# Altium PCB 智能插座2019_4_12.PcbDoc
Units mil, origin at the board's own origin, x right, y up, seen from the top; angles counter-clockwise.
Board outline 3149.61 x 3089.41 mil, 2 copper layers (Top Layer, Bottom Layer); 84 components, 62 nets, 274 pads, 96 vias.
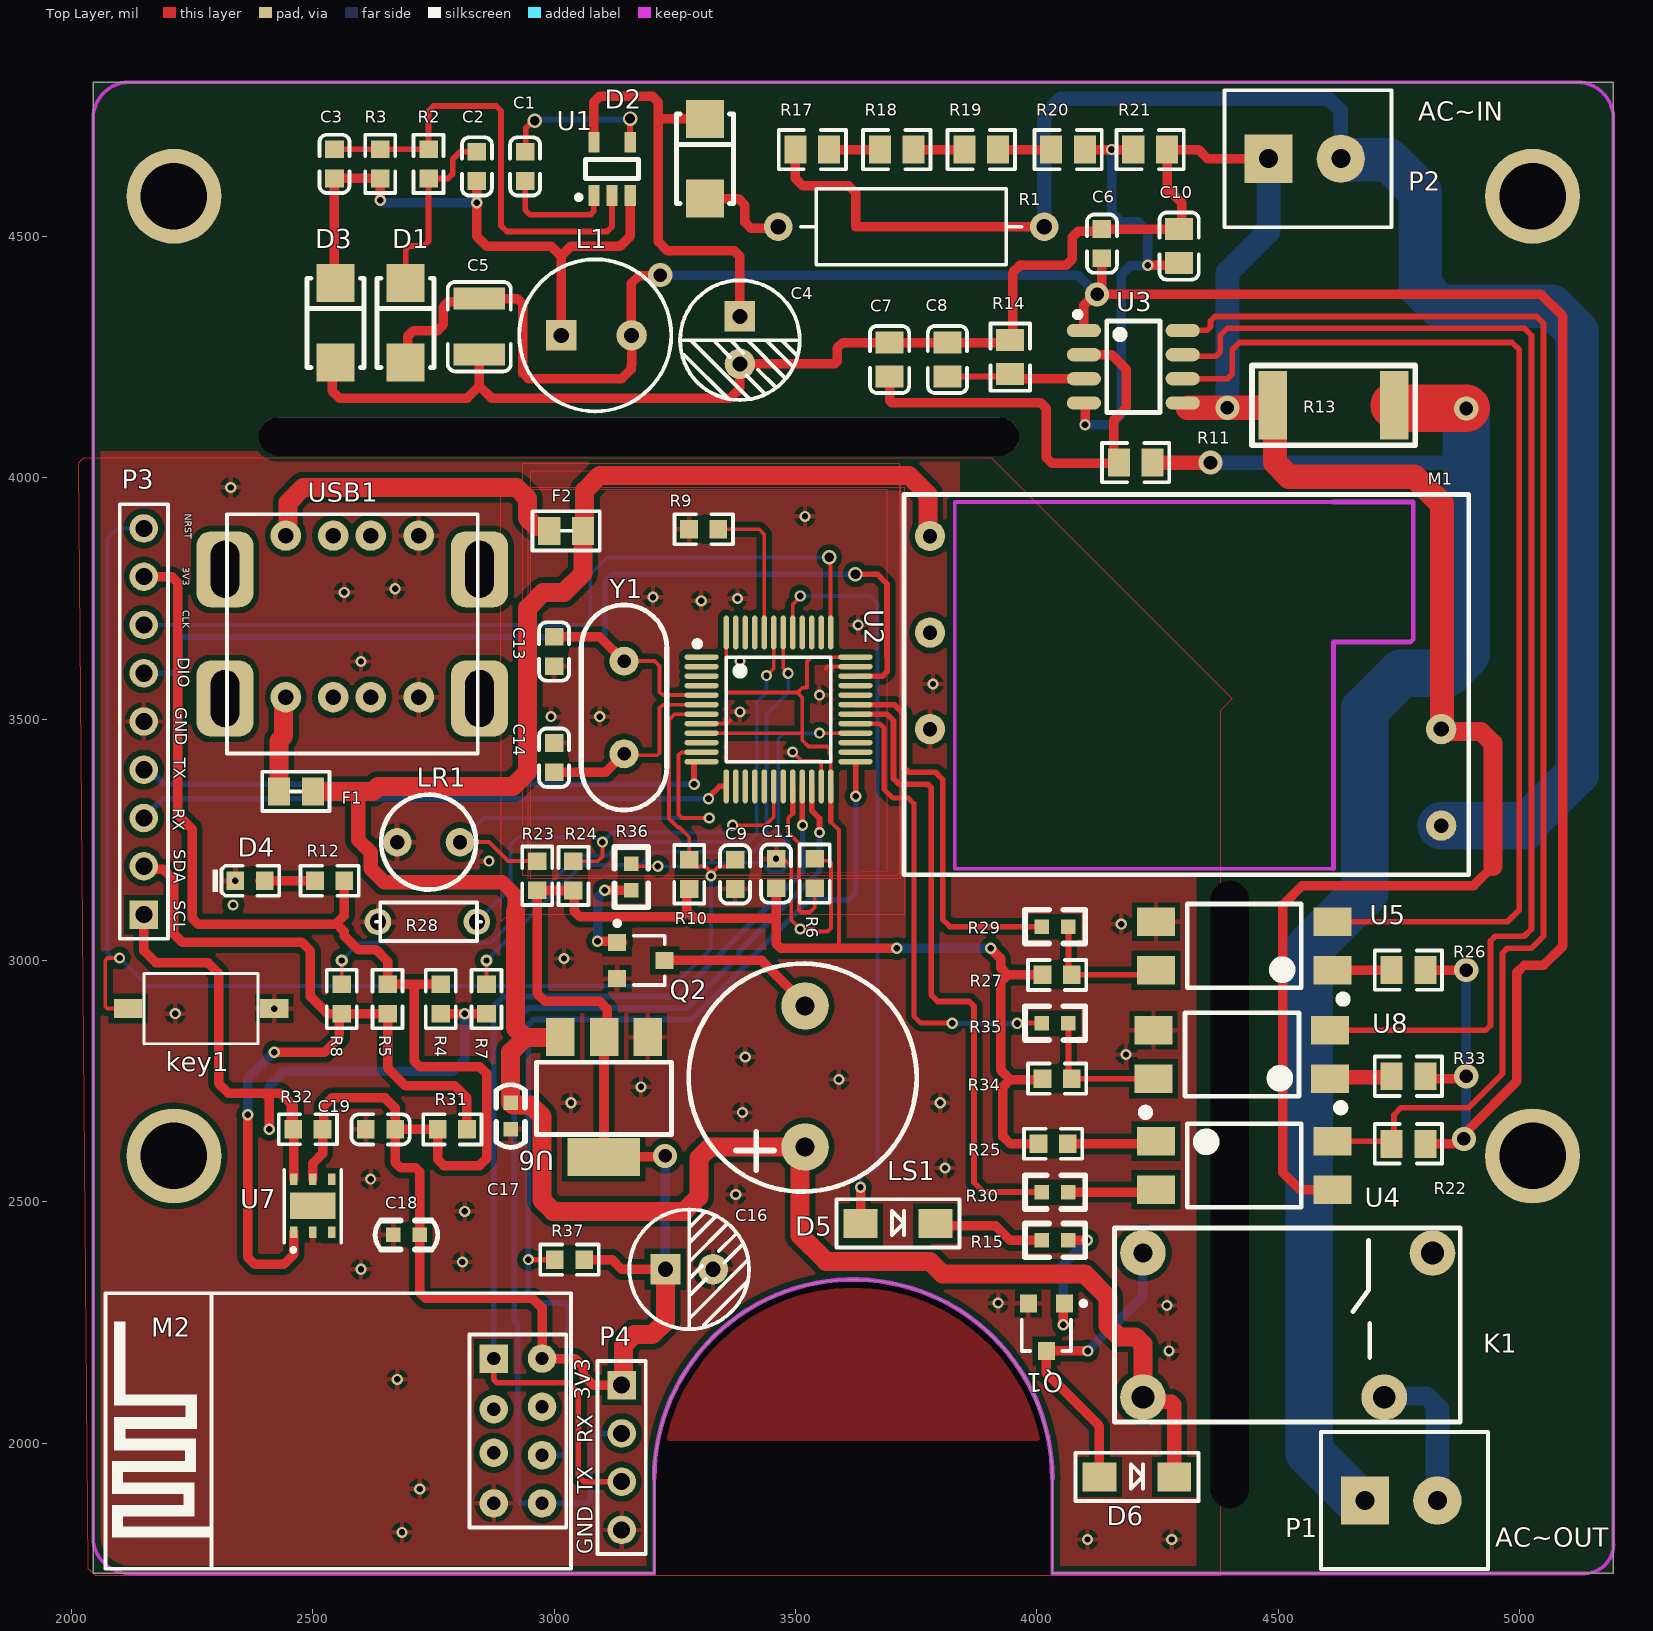
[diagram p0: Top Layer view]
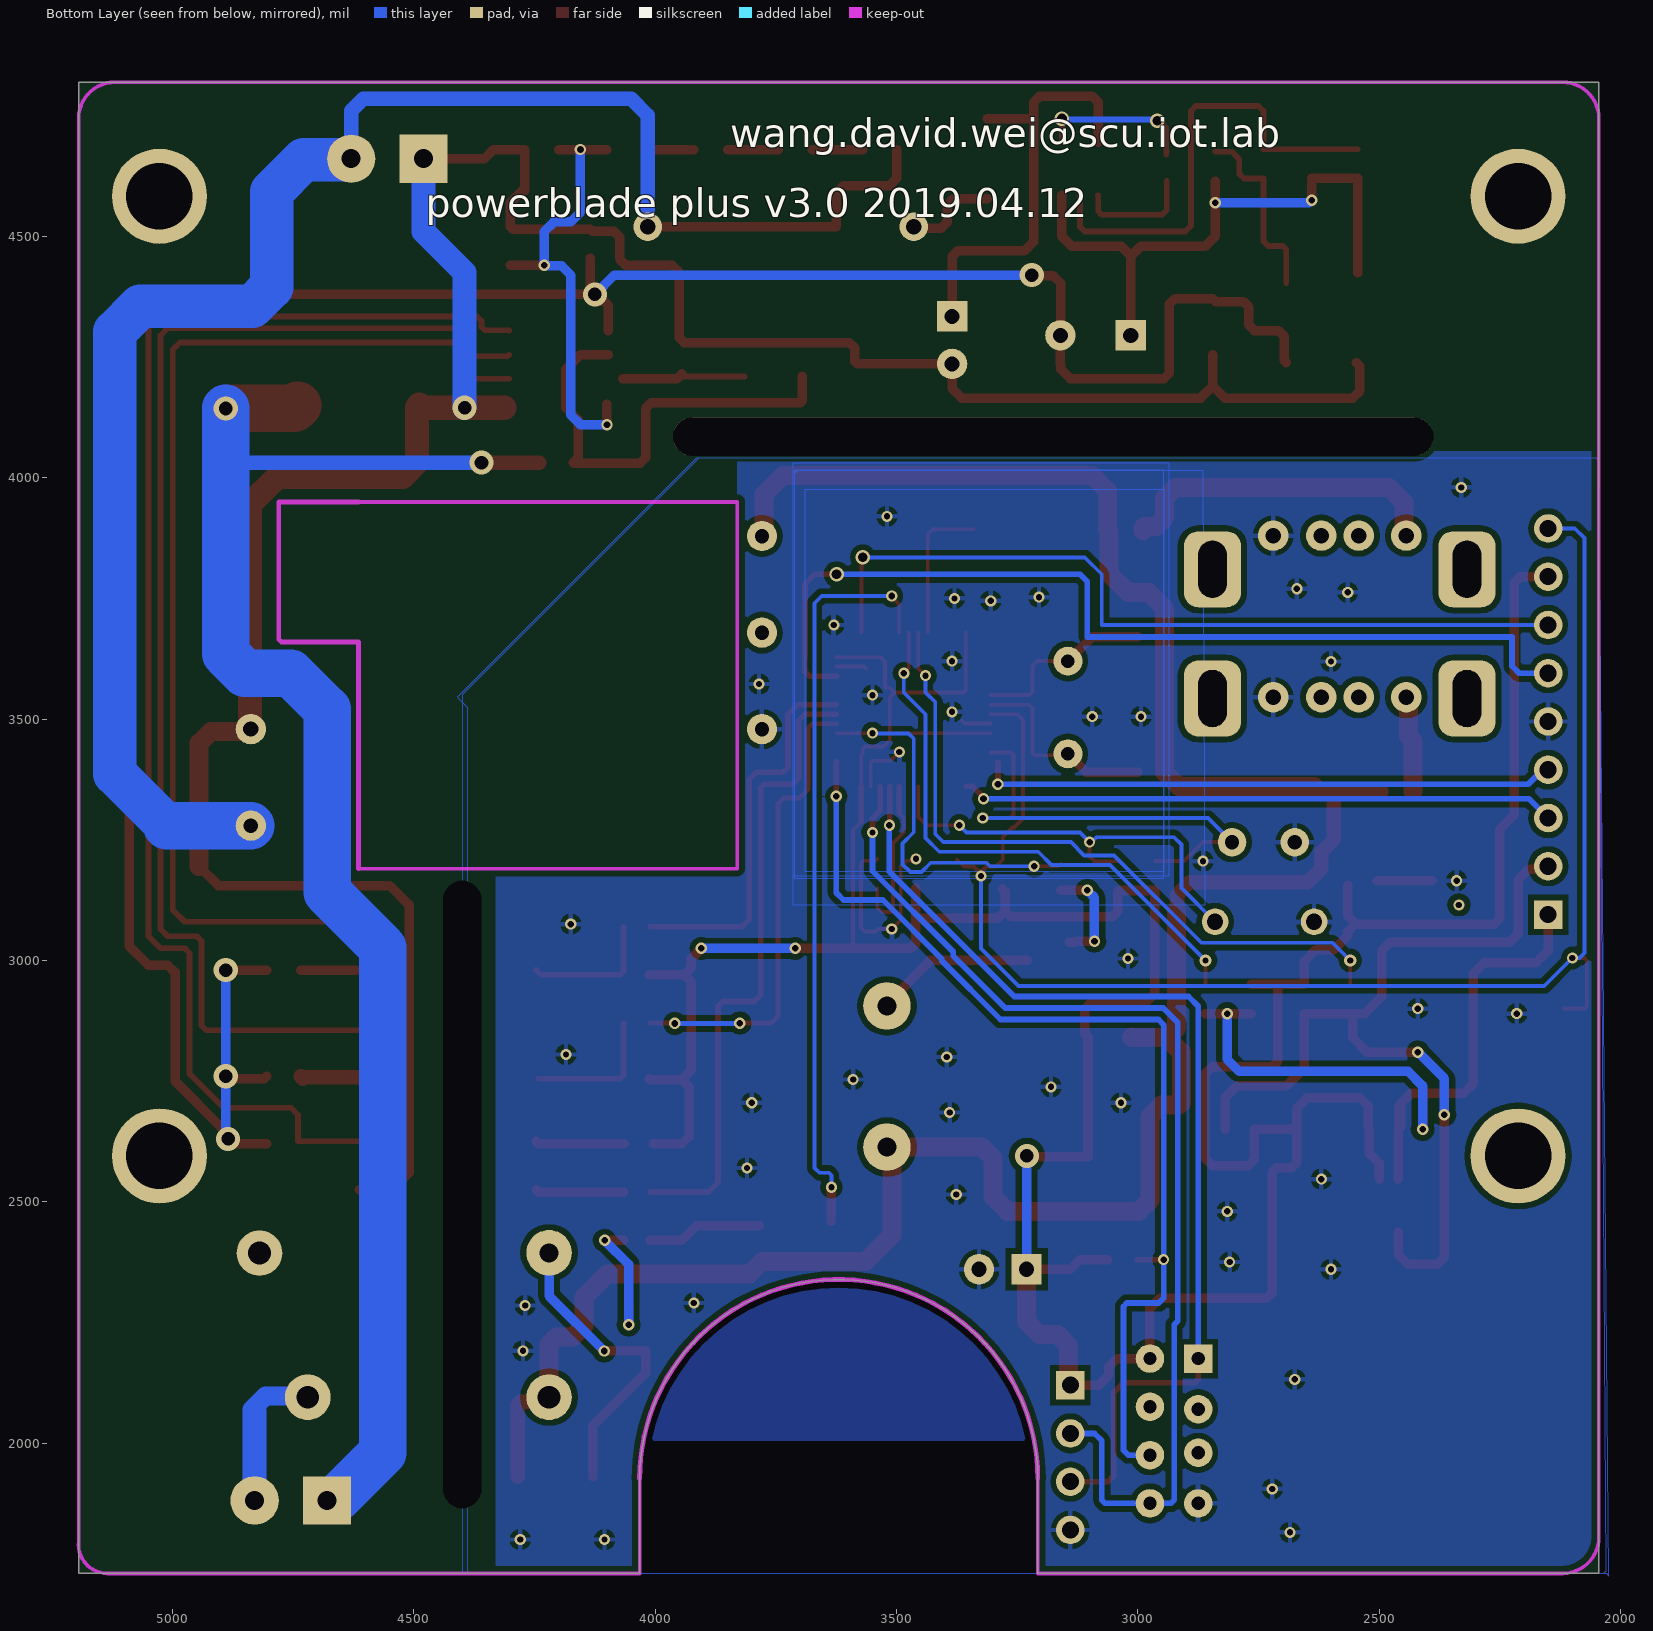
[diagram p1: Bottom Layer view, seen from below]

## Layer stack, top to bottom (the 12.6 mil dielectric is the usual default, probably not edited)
Top Solder: solder mask 0.4, Solder Resist, Dk 3.5
Top Layer: signal copper 1.4
Dielectric1: dielectric 12.6, FR-4, Dk 4.8
Bottom Layer: signal copper 1.4
Bottom Solder: solder mask 0.4, Solder Resist, Dk 3.5

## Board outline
2045,1730 2045,4819.41 5194.61,4819.41 5194.61,1730 4032.32,1730 4032.32,1925.71 ccw(c3619.84,1926.42) 3207.36,1925.71 3207.36,1730.04 3207.32,1730

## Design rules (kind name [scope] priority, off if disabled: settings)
Clearance [All] p1: gap=8 ignorepadtopadclearanceinfootprint=FALSE
ComponentClearance [All] p1 off: gap=10 collisioncheckmode=3 verticalgap=10 showdistances=FALSE
FabricationTestPointUsage TestPointUsage [All] p1: valid=0 allowmultiple=FALSE
FabricationTestpoint Testpoint [All] p1: side=3 testpointundercomponent=TRUE minsize=40 maxsize=100 preferedsize=60 minholesize=0 maxholesize=40 preferedholesize=32 testpointgrid=1 allowsidetop=TRUE allowsidebottom=TRUE usegrid=TRUE gridtolerance=0.01
PolygonConnect [All] p1: connectstyle=Relief reliefconductorwidth=10 reliefentries=4 polygonreliefangle="90 Angle" airgapwidth=10
RoutingVias [All] p1 off: holewidth=28 width=50 viastyle="Through Hole" minholewidth=28 minwidth=50 maxholewidth=28 maxwidth=50
SolderMaskExpansion [All] p1: expansion=4
Width [All] p1: maxlimit=308.11 minlimit=7.87 preferedwidth=19.68
27 further rules are at their usual default settings.

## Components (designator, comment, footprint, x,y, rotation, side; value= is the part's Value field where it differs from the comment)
C1 "2.2μF/10V" LC-0603_C 2940,4645 r270 top value="100nF (104) ±10% 50V"
C2 "220nF" LC-0603_C 2840,4645 r90 top value="100nF (104) ±10% 50V"
C3 "470pF" LC-0603_C 2545,4650.32 r90 top value="100nF (104) ±10% 50V"
C4 "3.3μF/400V" CAP-ELECT-TH-6.3X7 3385,4285 r270 top value=2.2μF/400V
C5 "100μF" LC-1210_C 2845,4313.07 r90 top value="100nF (104) ±10% 50V"
C6 "0.1μF" LC-0603_C 4135,4485 r90 top value="100nF (104) ±10% 50V"
C7 "33nF" LC-0805_C 3695,4245 r90 top value="100nF (104) ±10% 50V"
C8 "33nF" LC-0805_C 3815,4245 r270 top value="100nF (104) ±10% 50V"
C9 "0.1μF" LC-0603_C 3375,3178.37 r90 top
C10 "33nF" LC-0805_C 4295,4480 r90 top value="100nF (104) ±10% 50V"
C11 "0.1μF" LC-0603_C 3460,3180 r270 top
C13 "20pF" LC-0603_C 3000,3640 r270 top
C14 "20pF" LC-0603_C 3000,3420 r90 top
C16 "1000μF/400V" CAP-ELECT-TH-6.3X7 3280,2360 r0 top value=2.2μF/400V
C17 "104" 0603C#1 2911.26,2683.39 r90 top
C18 "104" 0603C#2 2700,2430 r0 top
C19 "0.1μF" LC-0603_C 2640.43,2649.96 r0 top
D1 "1N4007" LC-SMA(DO-214AC)_S1 2700,4320 r270 top
D2 "1N4007" LC-SMA(DO-214AC)_S1 3320,4660 r270 top
D3 "US1J(600V 1A)" LC-SMA(DO-214AC)_S1 2555,4320 r270 top
D4 "POWER" LC-0603_LED_S1 2370,3165 r0 top value=ºìÉ
D5 "IN4148" 1206D#1 3585,2425 r90 top
D6 "" 1206D#2 4080,1900 r90 top
F1 "1.1A  自恢复保险丝" AFUSE 2460,3360 r180 top
F2 "1.1A  自恢复保险丝" AFUSE 3020,3900 r180 top
K1 "Relay-5V" SJ-S-105LMH 4220,2197.36 r0 top
key1 "SW" KEY-2 2420,2900 r180 top
L1 "1mH" L-10X14 3085.32,4295 r0 top
LR1 "光敏电阻" GUANGMIN 2740,3245 r180 top
LS1 "BUZZER 5V" BUZZER 3520,2760 r270 top
M1 "ACDC_THX208based" ACDC_THX208 4895,3180 r180 top
M2 "ESP-01&01S Module" "ESP-01&01S Module" 2925,2025 r90 top
P1 "Header" 3.81-2P 4680,1880 r0 top
P2 "Header" 3.81-2P 4480,4660 r0 top
P3 "Header 9" HDR1X9 2150,3095 r90 top
P4 "Header 4" HDR1X4 3140,2120 r270 top
Q1 "S8050" SOT-23 4020,2240 r180 top
Q2 "S8050" SOT-23 3180,3000 r270 top
R1 "39Ω/1W" R-1W-THT 3740,4520 r180 top
R2 "5.49KΩ" LC-0603_R 2740,4650.32 r270 top
R3 "4.99KΩ" LC-0603_R 2640,4650.31 r90 top
R4 "4.7KΩ" LC-0603_R 2765,2920 r270 top
R5 "4.7KΩ" LC-0603_R 2655,2920 r270 top
R6 "10KΩ" LC-0603_R 3540,3180 r270 top
R7 "100" LC-0603_R 2860,2920 r90 top
R8 "100" LC-0603_R 2560,2920 r90 top
R9 "10KΩ" LC-0603_R 3310,3893.15 r180 top
R10 "10KΩ" LC-0603_R 3280,3178.37 r270 top
R11 "1KΩ,1%" LC-0805_R 4205,4031.46 r0 top
R12 "1.5KΩ" LC-0603_R 2535,3165 r0 top
R13 "2mΩ/25A" R2512 4615,4150 r180 top
R14 "1KΩ,1%" LC-0805_R 3945,4250 r90 top
R15 "Res2" 0603 4065.61,2420 r180 top value=4.7K
R17 "470KΩ,1%" LC-0805_R 3535,4680 r180 top
R18 "470KΩ,1%" LC-0805_R 3710,4680 r180 top
R19 "470KΩ,1%" LC-0805_R 3885,4680 r180 top
R20 "470KΩ,1%" LC-0805_R 4065,4680 r180 top
R21 "1KΩ,1%" LC-0805_R 4235,4680 r0 top
R22 "1KΩ,1%" LC-0805_R 4770,2620 r0 top
R23 "10KΩ 1%" LC-0603_R 2965,3175.32 r270 top
R24 "10KΩ 1%" LC-0603_R 3040,3175 r270 top
R25 "2.2KΩ" LC-0603_R 4033.99,2620 r180 top
R26 "1KΩ,1%" LC-0805_R 4769.96,2980 r0 top
R27 "2.2KΩ" LC-0603_R 4042.25,2970 r180 top
R28 "MF52-10K   3950 1％" AXIAL-0.3 2740,3080 r180 top value=MF52-10K
R29 "0Ω/1W" 0603 4065.61,3070 r180 top
R30 "0Ω/1W" 0603 4010.61,2520 r0 top
R31 "10KΩ" LC-0603_R 2789.17,2649.96 r0 top
R32 "10KΩ" LC-0603_R 2490,2650 r180 top
R33 "1KΩ,1%" LC-0805_R 4769.96,2760 r0 top
R34 "2.2KΩ" LC-0603_R 4042.25,2755 r180 top
R35 "0Ω/1W" 0603 4065.61,2870 r180 top
R36 "4.7K" 0603 3160,3200 r270 top
R37 "4.7KΩ" LC-0603_R 3031.94,2380 r0 top
U1 "MP150" LC-SOT-23-5 3120,4640 r270 top
U2 "STM32F103C8T6" LC-LQFP-48_7x7x05P 3465,3520 r270 top
U3 "HLW8032" LC-SOP-8_150mil 4200,4230 r270 top
U4 "PC817" LC-SMD-4 4430,2575 r0 top
U5 "PC817" LC-SMD-4 4430,3030 r180 top
U6 "LM1117-3.3V" SOT-223/P2.3 3105,2730 r270 top
U7 "SHT1" SHT2X 2500.04,2436.5 r0 top
U8 "PC817" LC-SMD-4 4425,2805 r180 top
USB1 "2_USB" 2_USB 2600,3880 r180 top
Y1 "8M" 49/U_N 3145,3620 r270 top value="25MHz ±20ppm 20pF"

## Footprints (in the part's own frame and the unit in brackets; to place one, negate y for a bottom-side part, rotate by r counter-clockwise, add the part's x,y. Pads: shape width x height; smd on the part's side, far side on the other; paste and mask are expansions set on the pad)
2_USB [mm]
  rrect50% 3x4 hole 1.5 slot 3 at 90 deg: 0(-6.24,8.57) 0(-6.24,1.77) 0(7.16,8.57) 0(7.16,1.77)
  round 1.6 hole 0.8: 1(3.96,8.5) 2(-0.508,8.5) 3(1.46,8.5) 4(-3.04,8.5) 5(3.96,0) 6(-0.508,0) 7(1.46,0) 8(-3.04,0)
  silkscreen extent -6.14,-1.13 7.06,11.47
3.81-2P [mil]
  rect 100x100 hole 39.37: 1(0,0.99)
  round 100 hole 39.37: 2(150,1)
  silkscreen extent -91,-141 255,143
49/U_N [mil]
  round 60 hole 28: 1(0,0) 2(192,0)
  silkscreen extent -116,-88 308,89, body extent -117,-88 309,89, height 512
0603 [mil]
  rect 30x30 smd: 1(0,0) 2(55,0)
  silkscreen extent -35,-35 90,35
0603C#1 [mil]
  rect 30x30 smd mask+4: 1(21.61,1.26)
  rect 30x30 smd: 2(-33.39,1.26)
  silkscreen extent -71,-29 59,31
0603C#2 [mil]
  rect 30x30 smd: 1(21.61,1.26) 2(-33.39,1.26)
  silkscreen extent -71,-29 59,31
1206D#1 [mil]
  rect 60x70 smd: 1(30,-50) 2(30,-205)
  silkscreen extent -20,-255 80,0
1206D#2 [mil]
  rect 60x70 smd: 1(30,-50)
  rect 60x70 smd mask+4: 2(30,-205)
  silkscreen extent -20,-255 80,0
ACDC_THX208 [mm]
  round 1.6 hole 0.762: 1(1.45,-2.52) 3(28.35,-7.6) 4(28.35,-12.68)
  round 1.6 hole 0.8: 2(1.45,-7.6)
  round 1.6 hole 0.762 mask+0.102: 5(28.35,-17.76)
  silkscreen extent 0,-19.94 29.72,0.06
AFUSE [mm]
  rect 1.16x1.47 smd mask+0.102: 1(-1.017,0.254)
  rect 1.16x1.47 smd: 2(0.763,0.254)
  silkscreen extent -1.9,-0.78 1.64,1.29, body extent -1.12,-0.37 0.88,0.88, height 0.49
AXIAL-0.3 [mm] "Resistor; 2 Leads"
  round 1.4 hole 0.85: 1(-2.54,0) 2(2.667,0)
  silkscreen extent -2.77,-1.02 2.77,1.02
BUZZER [mm]
  round 2.5 hole 1 mask+0.102: 1(3.728,0)
  round 2.5 hole 1: 2(-3.703,0)
  silkscreen extent -5.93,-6.12 6.07,5.87
CAP-ELECT-TH-6.3X7 [mm]
  rect 1.6x1.6 hole 0.8: 1(-1.25,0)
  round 1.6 hole 0.8: 2(1.25,0)
  silkscreen extent -3.15,-3.15 3.15,3.15
"ESP-01&01S Module" [mm]
  rect 1.5x1.5 hole 0.7: 1(3.81,1.27)
  round 1.5 hole 0.7: 2(1.15,1.27) 3(-1.15,1.27) 4(-3.81,1.27) 5(3.81,-1.27) 6(1.27,-1.27) 7(-1.27,-1.27) 8(-3.81,-1.27)
  silkscreen extent -7.25,-2.79 7.25,21.71
GUANGMIN [mm]
  round 1.5 hole 0.75: 1(-1.651,0) 2(1.651,0)
  silkscreen extent -2.5,-2.5 2.5,2.5
HDR1X4 [mm] "Connector; Header; 4 Position"
  rect 1.5x1.5 hole 0.9: 1(0,0)
  round 1.5 hole 0.9: 2(2.54,0) 3(5.08,0) 4(7.62,0)
  silkscreen extent -1.27,-1.27 8.89,1.27
HDR1X9 [mm] "Connector; Header; 9 Position"
  rect 1.5x1.5 hole 0.9: 1(0,0)
  round 1.5 hole 0.9: 2(2.54,0) 3(5.08,0) 4(7.62,0) 5(10.16,0) 6(12.7,0) 7(15.24,0) 8(17.78,0) 9(20.32,0)
  silkscreen extent -1.27,-1.27 21.59,1.27
KEY-2 [mm]
  rect 1.5x1 smd: 1(-0.005,-0.001) 2(7.685,-0.001)
  silkscreen extent 0.85,-1.85 6.85,1.86
L-10X14 [mm]
  rect 1.6x1.6 hole 0.8: 1(-1.786,0)
  round 1.6 hole 0.8: 2(1.913,0)
  silkscreen extent -4,-4 4,4
LC-0603_C [mm]
  rect 0.93x0.98 smd: 1(-0.77,0) 2(0.77,0)
  silkscreen extent -1.54,-0.79 1.54,0.79, body extent -0.8,-0.4 0.8,0.4, height 0.3
LC-0603_LED_S1 [mm]
  rect 0.93x0.98 smd: A(0.77,0) K(-0.77,0)
  silkscreen extent -1.97,-0.79 1.53,0.79, body extent -0.8,-0.4 0.8,0.4, height 0.6
LC-0603_R [mm]
  rect 0.93x0.98 smd: 1(-0.77,0) 2(0.77,0)
  silkscreen extent -1.53,-0.79 1.54,0.79, body extent -0.85,-0.4 0.85,0.4, height 0.56
LC-0805_C [mm]
  rect 1.16x1.47 smd: 1(-0.89,0) 2(0.89,0)
  silkscreen extent -1.77,-1.04 1.77,1.04, body extent -1,-0.62 1,0.63, height 0.77
LC-0805_R [mm]
  rect 1.16x1.47 smd: 1(-0.89,0) 2(0.89,0)
  silkscreen extent -1.77,-1.03 1.77,1.04, body extent -1,-0.62 1,0.63, height 0.49
LC-1210_C [mm]
  rect 1.16x2.72 smd: 1(-1.475,0) 2(1.475,0)
  silkscreen extent -2.36,-1.66 2.35,1.66, body extent -1.6,-1.25 1.6,1.25, height 1.3
LC-LQFP-48_7x7x05P [mm]
  oval 0.28x1.8 smd: 1(-2.75,-4.05) 2(-2.25,-4.05) 3(-1.75,-4.05) 4(-1.25,-4.05) 5(-0.75,-4.05) 6(-0.25,-4.05) 7(0.25,-4.05) 8(0.75,-4.05) 9(1.25,-4.05) 10(1.75,-4.05) 11(2.25,-4.05) 12(2.75,-4.05) 25(2.75,4.05) 26(2.25,4.05) 27(1.75,4.05) 28(1.25,4.05) 29(0.75,4.05) 30(0.25,4.05) 31(-0.25,4.05) 32(-0.75,4.05) 33(-1.25,4.05) 34(-1.75,4.05) 35(-2.25,4.05) 36(-2.75,4.05)
  oval 1.8x0.28 smd: 13(4.05,-2.75) 14(4.05,-2.25) 15(4.05,-1.75) 16(4.05,-1.25) 17(4.05,-0.75) 18(4.05,-0.25) 19(4.05,0.25) 20(4.05,0.75) 21(4.05,1.25) 22(4.05,1.75) 23(4.05,2.25) 24(4.05,2.75) 37(-4.05,2.75) 38(-4.05,2.25) 39(-4.05,1.75) 40(-4.05,1.25) 41(-4.05,0.75) 42(-4.05,0.25) 43(-4.05,-0.25) 44(-4.05,-0.75) 45(-4.05,-1.25) 46(-4.05,-1.75) 47(-4.05,-2.25) 48(-4.05,-2.75)
  silkscreen extent -3.6,-4.42 2.75,2.75
LC-SMA(DO-214AC)_S1 [mm]
  rect 2x2 smd: 1(2.076,-0.194) 2(-2.124,-0.194)
  silkscreen extent -2.37,-1.69 2.33,1.31
LC-SMD-4 [mm]
  rect 2x1.5 smd: 1(-4.65,1.27) 2(-4.65,-1.27) 3(4.65,-1.27) 4(4.65,1.27)
  silkscreen extent -5.4,-2.2 3,3, body extent -5.02,-2.42 5.01,2.42, height 3.9
LC-SOP-8_150mil [mm]
  oval 0.7x1.8 smd: 1(-1.905,-2.6) 2(-0.635,-2.6) 3(0.635,-2.6) 4(1.905,-2.6) 5(1.905,2.6) 6(0.635,2.6) 7(-0.635,2.6) 8(-1.905,2.6)
  silkscreen extent -2.9,-3.07 2.4,1.4, body extent -2.5,-3.1 2.5,3.1, height 1.75
LC-SOT-23-5 [mm]
  rect 1.1x0.6 smd: 1(1.4,-0.95) 2(1.4,0) 3(1.4,0.95) 4(-1.4,0.95) 5(-1.4,-0.95)
  silkscreen extent -0.5,-1.87 1.62,1.4
R2512 [mm]
  rect 1.5x3.6 smd: 1(-3.2,0) 2(3.2,0)
  silkscreen extent -4.3,-2.1 4.3,2.1
R-1W-THT [mm]
  round 1.5 / inner oval 1.5x2 / far side round 1.5 hole 0.8: 1(-7,0)
  round 1.5 hole 0.8: 2(7,0)
  silkscreen extent -5.8,-2 5.8,2
SHT2X [mm]
  rect 2.4x1.4 smd: 0(0,1.4)
  rect 0.4x0.6 smd: 1(-1,0) 2(0,0) 3(1,0) 4(1,2.8) 5(0,2.8) 6(-1,2.8)
  silkscreen extent -1.5,-0.95 1.5,3.3
SJ-S-105LMH [mm]
  round 2.4 hole 1: 1(0,5)
  round 2.4 hole 1.2 mask+0.102: 2(0,-2.6)
  round 2.4 hole 1.2: 3(15.24,4.984) 4(12.7,-2.6)
  silkscreen extent -1.5,-3.9 16.7,6.3
SOT-23 [mm] "SOT-23; 3 Leads; Body 3.0 x 2.6 mm, inc. leads (LxW max)"
  rect 0.9x0.95 smd: 1(-0.95,-1.25) 2(0.95,-1.25) 3(0,1.25)
  silkscreen extent -2.08,-1.37 1.3,1.25
SOT-223/P2.3 [mil]
  rect 79x59 smd: 1(-111,89.1) 2(-111,-1.45)
  rect 79x150 smd: 2(137,-1.9)
  rect 79x59 smd mask+4: 3(-111,-92)
  silkscreen extent -59,-141 91,139

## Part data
C1 C2 C3 C5 C6 C7 C8 C10: library part CAP, "贴片电容"
C4 C16: library part "Cap Pol1", "直插电解电容"
C9 C11 C13 C14 C19: library part Cap, "贴片电容"
C17 C18: library part CAP, "Capacitor"
D1 D2 D3: library part "Diode 1N5408", "贴片二极管"
D4: library part LED1, "发光二极管"
D5 D6: library part Diode, "Default Diode", PackageDocument=Sep-1996
F1 F2: library part "Fuse 2", "Fuse"
K1: library part SJ-S-105LMH, "Single-Pole Dual-Throw Relay"
key1: "Switch"
L1: library part IND_8, "直插绕线电感"
LS1: library part Bell, "Electrical Bell"
M1: library part ACDC, "THX208Based"
P1 P2: library part "Header 2", "Header, 2-Pin"
P3: "Header, 9-Pin"
P4: "Header, 4-Pin"
Q1 Q2: library part NPN, "NPN Bipolar Transistor"
R1 R2 R3 R4 R5 R6 R7 R8 R9 R10 R11 R12 R13 R14 R17 R18 R19 R20 R21 R22 R23 R24 R25 R26 R27 R29 R30 R31 R32 R33 R34 R35: library part 电阻, "贴片电阻"
R15: "Resistor"
R28: library part "Res Adj2", "Variable Resistor"
R36: library part Res2, "Resistor"
R37: library part "0805 62KΩ (6202) 1%", "贴片电阻", Package=0402, SuppliersPartNumber=C17783
U1 U3: "IC"
U2: library part STM32F103CBT6, "IC"
U4 U5 U8: library part PS2501L-1-F3-A, "IC"
U6: library part 1117
U7: library part SHT21
Y1: library part XTAL_1, "晶振（直插）"

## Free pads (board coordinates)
  round 196.85 hole 137.8: 0(2212.32,2595) 0(2212.32,4583.19) 0(5027.28,2595) 0(5027.28,4583.19)
  oval 1574.8x78.74 hole 78.74 slot 1574.8 at 0 deg unplated paste+0: 0(3175.55,4085)
  oval 78.74x393.7 hole 78.74 slot 1300 at 90 deg unplated paste+0: 0(4400,2515)

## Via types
v1: diameter 23, hole 13, Top Layer to Bottom Layer, 60 vias
v2: diameter 23.62, hole 13.78, Top Layer to Bottom Layer, 21 vias
v3: diameter 50, hole 28, Top Layer to Bottom Layer, 9 vias
v4: diameter 30, hole 20, Top Layer to Bottom Layer, 4 vias
v5: diameter 25, hole 13, Top Layer to Bottom Layer, 2 vias

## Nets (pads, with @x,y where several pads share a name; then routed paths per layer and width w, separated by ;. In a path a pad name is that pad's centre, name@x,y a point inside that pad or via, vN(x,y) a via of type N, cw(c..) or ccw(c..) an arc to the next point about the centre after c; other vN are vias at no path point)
+3.3V: C11.2 C16.1 C18.1 C19.2 M2.5 P3.8 P4.1 R4.1 R5.1 R10.2 R12.2 R23.2 R24.2 R25.2 R27.2 R31.1 R32.1 R34.2 R37.2 U2.9 U2.24 U2.36 U2.48 U6.2 U7.5 | length 8123.6
  Top Layer w7.87: U2.9 3514.21,3470.79 ; U2.48 3356.73,3559.61 3361.35,3555 3504.21,3555 ; 3573.27,3286.73 3590,3270 3590,3025 ; U2.24 3573.27,3418.51 3573.08,3418.7 3573.08,3425.39 3570.04,3428.43 3570.04,3438.74 3565.43,3443.35 3526.97,3443.35 3514.21,3456.11 3514.21,3470.79 ; U2.36 3533.27,3628.27 3524.21,3619.21 3524.21,3565 3514.21,3565 3504.21,3555 ; 3504.21,3555 3514.21,3545 3514.21,3470.79
  Top Layer w11: 3573.27,3286.73 U2.24
  Top Layer w19.68: P3.8 2150.59,3794.41 2208.47,3794.41 2220,3782.88 2220,3302.01 2250,3272.01 2250,3087.54 2262.54,3075 2548.73,3075 ; U7.5 2500,2546.77 2500,2579.41 2520.31,2599.72 R32.1 2523.23,2652.92 2523.23,2698.82 2539.41,2715 2650,2715 2670.75,2694.25 C19.2 ; R12.2@2565.32,3156.18 2565.32,3092.86 2548.73,3076.27 2565,3060 2565,3051.35 2593.85,3022.5 2630.65,3022.5 2655,2998.15 R5.1 ; R5.1@2659.68,2950.32 2710,2950.32 ; C18.1 2721.61,2561.85 2713.47,2570 2682.28,2570 2670.75,2581.53 C19.2 ; 2733.15,2300 2955.16,2300 2975,2280.16 M2.5 3043.79,2175 3060,2158.79 3060,2140.94 3080.94,2120 P4.1 ; R4.1 2710,2950.32 ; R24.2 3042.25,3142.43 3042.25,3101.53 3053.79,3090 3263.47,3090 3275,3101.53 ; R37.2 3120,2380 3140,2360 C16.1 ; U6.2@3103.55,2593.45 3103.1,2593 3228,2593 v3(3230,2595) ; R10.2 3275,3143.06 3275,3101.53 ; C11.2 3460,3087.54 ; v2(3710,3025) 3590,3025 3470,3025 3460,3035 3460,3087.54 ; v2(3905,3025) 3905,3023.93 3925,3003.93 3925,2985 3940,2970 ; R25.2 3945,2620 3930,2635 3930,2738.07 3945,2753.07 ; R34.2 4010,2753.07 3945,2753.07 ; R27.2 3940,2970 ; C19.2 R31.1 2758.86,2587.67 2771.53,2575 2845.59,2575 2860,2589.41 2860,2765.67 2845.67,2780 2721.53,2780 2710,2791.53 2710,2950.32 ; 3275,3101.53 3276.01,3101.53 3290,3087.54 3460,3087.54 ; 3940,2970 3925,2955 3925,2773.07 3945,2753.07
  Top Layer w20: C18.1 2721.61,2311.53 2733.15,2300 ; R24.2 3039.84,3144.84 2965.16,3144.84 R23.2 2965,2931.72 2981.72,2915 3094.68,2915 3110,2899.68 3110,2847.45 3103.55,2841 U6.2@3103.55,2593.45
  Top Layer w39.37: P4.1 3143.58,2123.58 3143.58,2201.94 3166.65,2225 3204.21,2225 3230.79,2251.58 C16.1
  Bottom Layer w19.68: v3(3230,2595) 3230.79,2594.21 C16.1 ; v2(3710,3025) v2(3905,3025)
+5V: C17.1 D6.2 F1.1 F2.1 K1.2 LS1.1 M1.5 U6.3 | length 5209.9
  Top Layer w30: 2590,3350 2593.85,3346.15 2593.85,3250 2620,3223.85 2620,3190 2648.06,3161.94 2893.06,3161.94 2918.71,3136.29 2918.71,3115.51 2920,3114.22 2920,3102.63 ; K1.2@4220,2097.64 4232.34,2085.3 4279.77,2085.3 4285,2080.06 D6.2
  Top Layer w39.37: F1.1 2590,3350 2625,3350 2635,3360 2914.45,3360 2945,3390.55 2945,3730 2977.5,3762.5 3020.53,3762.5 3060.04,3802.01 F2.1 3063.19,3893.15 3063.19,3973.19 3095,4005 3735,4005 3774.34,3965.66 3774.34,3883.73 M1.5 ; 2920,3102.63 2920,2859.81 2940,2839.81 ; U6.3 3013,2839.81 2940,2839.81 ; K1.2@4220,2097.64 4220,2205 4205,2220 4170.56,2220 4147.5,2243.06 4147.5,2302.5 4100,2350 3805,2350 3778.45,2376.55 3563.45,2376.55 3510,2430 3510,2603.22 3500,2613.22 3323.06,2613.22 3300,2590.16 3300,2510 3270,2480 2998.06,2480 2975,2503.06 2975,2676.94 2951.94,2700 2915,2700 C17.1 2910,2809.81 2940,2839.81
A+5V: C5.2 C6.1 D1.1 L1.2 R22.2 R26.2 R33.2 U3.1 | length 5446.4
  Top Layer w19.68: D1.1 2697.2,4243.11 2697.2,4293.47 2708.73,4305 2758.47,4305 2770,4316.53 2770,4353.47 2781.53,4365 2838.86,4365 C5.2 2923.47,4371.14 2935,4359.61 2935,4216.53 2946.53,4205 3140,4205 3160,4225 3160,4233.35 3160.63,4233.98 L1.2 ; L1.2@3160,4305 3160,4403 3175.55,4418.55 3218.55,4418.55 v3(3220,4420) ; U3.1 4097.64,4357.64 v3@4122.5,4382.5 ; v3(4125,4380) 5045,4380 5090,4335 5090,3030 5050,2990 5010,2990 4995,2975 4995,2750 4895,2650 4895,2648.2 4885,2638.2 v3(4885,2630) 4875,2620 R22.2 ; v3@4135,4395 C6.1 ; R33.2 4810,2755 4885,2755 v3(4890,2760) ; R26.2 v3(4890,2980)
  Bottom Layer w19.68: v3(3220,4420) 4085,4420 v3(4125,4380) ; v3(4885,2630) 4890,2635 v3(4890,2760) v3(4890,2980)
AC220V-L: M1.1 P2.2 R1.1 R17.2 | length 3622.8
  Top Layer w19.68: R17.2 3499.96,4620.04 3515,4605 3610,4605 3625,4590 3625,4520 R1.1
  Bottom Layer w30: R1.1 4015.59,4750.59 4050,4785 4605,4785 4630,4760 P2.2
  Bottom Layer w90: P2.2 4631.91,4659.09 4728.19,4659.09 4795,4592.28 4795,4395 4835,4355 5067.28,4355 5120,4302.28 5120,3386.97 5012.25,3279.21
  Bottom Layer w98.43: M1.1 5012.25,3279.21
AC220V-N: C4.2 C5.1 C6.2 C7.2 C8.1 C10.2 D3.1 M1.2 P2.1 R13.2 R14.2 R21.2 U3.5 U4.3 | length 5820.2
  Top Layer w19.68: D3.1 2540,4230.91 2540,4180 2555,4165 2820,4165 2845,4190 ; C5.1 2845,4190 ; R21.2 4270,4595 4275,4595 4300,4570 4300,4520.04 C10.2 4294.73,4515.31 C6.2 4130.87,4511.18 4086.18,4511.18 4073.78,4498.78 4073.78,4453.46 4060.32,4440 3965,4440 3950,4425 3950,4290.04 R14.2 3940,4280.04 C8.1 C7.2 3598.01,4280.04 3586.48,4268.51 3586.48,4241.48 3580.78,4235.78 C4.2 3385,4185 3365,4165 2870,4165 2845,4190 ; R21.2 4335,4680 4354.01,4660.99 P2.1 ; v3@4385,4145 v3(4395,4145) ; R13.2@4484.02,4145 R13.2 R13.2@4490,4150.98 ; U4.3 4545,2525 4510,2560 4510,3115 4550,3155 4905,3155 4945,3195
  Top Layer w39.37: M1.2 4842.43,3474.69 4920.31,3474.69 4945,3450 4945,3195
  Top Layer w50: U3.5@4312.36,4145 v3@4385,4145 ; v3(4395,4145) R13.2@4484.02,4145 ; R13.2 4493.54,4145.47 4493.54,4031.46 4522.83,4002.17 4782.83,4002.17 4840,3945 M1.2@4840,3480 ; R13.2@4489.02,4151.97 R13.2@4490,4150.98
  Bottom Layer w50: v3(4395,4145) 4395,4425 4480,4510 P2.1
ADC_IN1: LR1.1 R23.1 U2.11 | length 953.6
  Top Layer w7.87: LR1.1 2865,3245 2904.37,3205.63 R23.1 ; U2.11 3304.95,3430.82 3263.3,3430.82 3257.87,3425.39 3257.87,3302.13 3265,3295 v1(3321.53,3295)
  Bottom Layer w7.87: LR1.1 2855,3295 v1(3321.53,3295)
ADC_IN8: R24.1 R28.1 U2.18 | length 923.5
  Top Layer w7.87: R24.1 3090,3205.31 3100,3215.32 v1(3100,3245) ; v1(3370,3280) 3438.27,3280 3455.16,3296.89 U2.18
  Bottom Layer w7.87: R28.1 2910,3150 2910,3240 2925,3255 3085.91,3255 3095.91,3245 v1(3100,3245) 3120,3265 3355,3265 v1(3370,3280)
BOOT0: R9.1 U2.44 | length 302.7
  Top Layer w7.87: R9.1 3425,3893.15 3435.47,3882.67 U2.44
CTL_PIN: D5.1 U2.41 | length 1554.4
  Top Layer w7.87: U2.41 3494.53,3737.06 3510,3752.54 v2(3510,3755)
  Top Layer w19.68: D5.1@3635,2460 v1(3635,2530)
  Bottom Layer w7.87: v2(3510,3755) 3655,3755 3670,3740 3670,2570 3660,2560 3640,2560 3635,2555 3635,2553.63 ; v1(3635,2530) 3635,2553.62
DGND: C9.1 C11.1 C13.2 C14.2 C16.2 C17.2 C18.2 C19.1 D4.K key1.1 LR1.2 M1.3 M2.4 P3.5 P4.4 Q1.2 Q2.2 R6.1 R9.2 R28.2 U2.8 U2.23 U2.35 U2.47 U5.3 U6.1 U7.2 U8.3 USB1.4 USB1.8 | length 659.9
  Top Layer w8: U2.8 3358.17,3490.47 3365,3497.31 ; v1(3460,3210.32) 3463.83,3206.49 3479.34,3206.49 3491.29,3194.54 3491.29,3083.71 v1(3510,3065) 3537.57,3065 3543.07,3059.5 3566.58,3059.5 3574.06,3066.99 3574.06,3201.8 3569.38,3206.49 3543.82,3206.49 R6.1 ; v1(3494.27,3431.74) 3512.43,3413.58 3550,3413.58 3553.58,3410 U2.23 ; 3562.99,3605 3566.58,3608.58 U2.35
  other v1: 4105,1800 4279.77,1800 2685,1815 2721.61,1905 2675,2131.92 4274.07,2191 4269.5,2285 3920,2290 2600,2360 2810,2375 2815,2480 3376.42,2515 2620,2546.73 3810,2570 3390,2685 3035,2705 3800,2705 3180,2738.07 3590,2753.07 3396.1,2800 4185,2805 2215,2889.69 2420.19,2900.03 3020.53,3003.93 4175,3075 2339.68,3165 2865,3205.63 2993.74,3505 3094.68,3505 3385,3515 3550,3549.53 3785,3572.48 2600,3619.21 3385,3620 3630,3695 3304.95,3745 3380,3750 3205,3752.54 2565.32,3762.5 2670.75,3770 3520,3920 2330,3980
I2C1_SCL: P3.1 R4.2 R7.1 R32.2 U7.6 | length 1647.3
  Top Layer w19.68: P3.1 2150,3020 2175,2995 2283.15,2995 2305,2973.15 2305,2745 2325,2725 2400,2725 ; v2(2410,2650) 2410,2715 2400,2725 ; U7.6 2460.18,2547.23 2460.18,2649.51 2455,2654.68 2455,2703.5 ; R32.2@2460.63,2649.05 R32.2 2459.68,2698.82 2455,2703.5 ; R4.2 v2(2815,2889.69) R7.1 ; 2400,2725 2433.5,2725 2455,2703.5
  Bottom Layer w19.68: v2(2410,2650) 2410,2740 2440,2770 2790,2770 2815,2795 v2(2815,2889.69)
I2C1_SDA: P3.2 R5.2 R8.1 R31.2 U7.1 | length 1921.4
  Top Layer w19.68: P3.2 2156.53,3188.47 2190.59,3188.47 2212.32,3166.73 2212.32,3055 2229.92,3037.4 2477.6,3037.4 2495,3020 2495,2925 2530.31,2889.69 R8.1@2555,2889.69 ; v2(2365,2680) 2365,2385 2380,2370 2440,2370 2460.67,2390.67 U7.1 ; v2(2420,2810) 2525,2810 2555,2840 R8.1@2555,2889.69 ; R31.2 2819.49,2715 2794.49,2740 2692.36,2740 2655,2777.36 R5.2 R8.1 R8.1@2555,2889.69
  Bottom Layer w19.68: v2(2365,2680) 2365,2755 v2(2420,2810)
L_LINE: K1.3
L_OUT: K1.4 P1.2 | length 339.5
  Bottom Layer w39.37: K1.4@4730.55,2087.09 4720,2097.64 4807.36,2097.64 4835,2070 4830,2065 ; P1.2 P1.2@4835,1886
  Bottom Layer w50: P1.2 4830,2065
NetC1_1: C1.1 U1.4 | length 329.5
  Top Layer w11.81: C1.1@2940,4676.9 C1.1@2940.79,4676.11 ; C1.1@2941.58,4669.53 2941.58,4725 2956.58,4740 v4(2960,4740) ; U1.4 v4(3157.4,4744.21)
  Bottom Layer w11.81: v4(2960,4740) 2962.11,4742.11 3155.3,4742.11 v4(3157.4,4744.21)
NetC1_2: C1.2 U1.1 | length 241.9
  Top Layer w11.81: C1.2 2940,4555 2950,4545 3075,4545 3081.92,4551.92 3081.92,4584.2 U1.1
NetC2_1: C2.1 C3.1 D3.2 L1.1 R3.1 U1.3 | length 1242
  Top Layer w19.68: D3.2@2545,4425 C3.1 R3.1 v2(2640,4575) ; C2.1 v2(2840,4570) 2840,4500 2860,4480 2993.74,4480 3014.37,4459.37 ; L1.1@3014.37,4305 3014.37,4459.37 ; U1.3 3157.4,4500.16 3137.24,4480 3035,4480 3014.37,4459.37
  Bottom Layer w19.68: v2(2640,4575) 2645,4570 v2(2840,4570)
NetC2_2: C2.2 D1.2 R2.2 | length 394.2
  Top Layer w11.81: D1.2 2692.36,4472.36 2700,4480 2730,4480 2740,4490 R2.2 2780,4620 2790,4630 2790,4660 2805.31,4675.31 C2.2
NetC3_2: C3.2 R2.1 R3.2 U1.2 | length 974.6
  Top Layer w11.81: C3.2 R3.2 R2.1 2740,4760 2750,4770 2880,4770 2890,4760 2890,4522.12 2902.12,4510 3110,4510 3120,4520 U1.2
NetC4_1: C4.1 D2.2 U1.5 | length 918.3
  Top Layer w19.68: U1.5 3082.68,4695.2 3082.68,4778.47 3094.21,4790 3204.26,4790 3215.79,4778.47 3215.79,4744.21 ; D2.2 3311.77,4744.21 3215.79,4744.21 ; C4.1 3385,4458.47 3373.47,4470 3235,4470 3215.79,4489.21 3215.79,4744.21
NetC7_1: C7.1 R11.1 U3.2 | length 946.9
  Top Layer w19.68: C7.1 3695,4160 3700,4155 4008.47,4155 4020,4143.47 4020,4041.53 4031.53,4030 4168.5,4030 R11.1 4160,4041.42 4160,4120 4185,4145 4185,4225 4155,4255 U3.2
NetC8_2: C8.2 R14.1 U3.3 | length 251.8
  Top Layer w11.81: C8.2 R14.1@3940,4209.96
  Top Layer w19.68: R14.1 3954.96,4205 U3.3@4067.64,4205
NetC10_1: C10.1 R20.1 R21.1 U3.4 | length 940.7
  Top Layer w19.68: v2(4100,4110) U3.4@4100,4152.64 ; R20.1 R21.1 ; v2(4230,4440) C10.1@4300,4440
  Bottom Layer w19.68: v2(4100,4110) 4155,4110 4175,4130 4175,4420 4194.25,4439.25 4229.25,4439.25 v2(4230,4440) 4230,4510 4210,4530 4175,4530 4155,4550 v2(4155,4680)
NetD2_1: D2.1 R1.2 | length 199.3
  Top Layer w19.68: D2.1 3381.73,4578.27 3395,4565 3395,4529.59 3407.47,4517.12 3461.53,4517.12 R1.2
NetD4_A: D4.A R12.1 | length 114.7
  Top Layer w19.68: D4.A@2390,3165 R12.1
NetD5_2: D5.2 R15.2 | length 238
  Top Layer w19.68: D5.2@3785,2450 3915,2450 3945,2420 R15.2
NetD6_1: D6.1 K1.1 Q1.3 | length 645.5
  Top Layer w19.68: v2(4105.79,2190.79) Q1.3 4020,2145 4130,2035 D6.1
  Bottom Layer w19.68: v2(4105.79,2190.79) 4220,2305 K1.1@4220,2396.85
NetF1_2: F1.2 USB1.1 | length 201.2
  Top Layer w39.37: F1.2 2429.96,3455 2439.57,3464.61 2439.57,3540.83 USB1.1
NetF2_2: F2.2 USB1.5 | length 689.5
  Top Layer w39.37: USB1.5 2448.61,3884.52 2448.61,3948.61 2480,3980 2921.92,3980 2944.98,3956.94 2944.98,3916.21 2961.94,3899.25 2986.81,3899.25 2989.96,3896.1 F2.2
NetLS1_2: LS1.2 Q2.3 | length 343.1
  Top Layer w19.68: Q2.3 3430,3000 3520,2910 LS1.2@3520,2895
NetP1_1: P1.1 R11.2 R13.1 | length 3291.3
  Top Layer w30: R11.2 v3(4360,4031.46)
  Top Layer w98.43: R13.1 4747.52,4143.47 v3(4890,4143.47)
  Bottom Layer w30: v3(4360,4031.46) 4890,4031.46
  Bottom Layer w98.43: P1.1@4660.91,1884.09 4565,1980 4565,3026.61 4680,3141.61 4680,3520.41 4680.41,3520.41 4755,3595 4850,3595 4890,3635 4890,4031.46 v3(4890,4143.47)
NetQ1_1: Q1.1 R15.1 | length 276.9
  Top Layer w19.68: v2(4055,2245) Q1.1@4055,2286.81 ; R15.1 v2(4105,2420)
  Bottom Layer w19.68: v2(4055,2245) 4055,2370 v2(4105,2420)
NetQ2_1: Q2.1 R36.2 | length 216
  Top Layer w19.68: v2(3090,3040) Q2.1@3128.19,3040 ; v2(3105,3145) R36.2 ; Q2.1 Q2.1@3142.4,3037.4
  Bottom Layer w19.68: v2(3090,3040) 3090,3130 v2(3105,3145)
NetR6_2: R6.2 U2.20 | length 347.8
  Top Layer w7.87: 3494.53,3304.53 3485,3295 3485,3265 3507.23,3242.77 3507.23,3104.61 3511.84,3100 3530.39,3100 3540,3109.61 R6.2
  Top Layer w11: 3494.53,3304.53 U2.20
NetR17_1: R17.1 R18.2 | length 104.9
  Top Layer w19.68: R17.1 R18.2
NetR18_1: R18.1 R19.2 | length 104.9
  Top Layer w19.68: R18.1 R19.2
NetR19_1: R19.1 R20.2 | length 100
  Top Layer w19.68: R19.1 R20.2@4020,4680
NetR25_1: R25.1 U4.1 | length 184.7
  Top Layer w19.68: R25.1 4241.93,2620 U4.1
NetR26_1: R26.1 U5.1 | length 114.9
  Top Layer w19.68: U5.1@4620,2980 R26.1
NetR27_1: R27.1 R29.1 U5.4 | length 281.4
  Top Layer w11.81: R29.1 4065.61,2976.95 R27.1 4236.93,2970 U5.4
NetR30_2: R30.2 U4.2 | length 183.4
  Top Layer w19.68: R30.2 4241.93,2520 U4.2
NetR33_1: R33.1 U8.1 | length 136
  Top Layer w30: U8.1 4610.57,2757.5 4732.42,2757.5 R33.1 4734.92,2759.92 R33.1@4730,2755
NetR34_1: R34.1 R35.1 U8.4 | length 287.2
  Top Layer w11.81: R35.1 4065.61,2761.95 R34.1 U8.4
NRST: C9.2 key1.2 P3.9 R10.1 U2.7 | length 3076.3
  Top Layer w7.87: v1(2100,3005) 2075,3005 2070,3000 2070,2904.64 2074.61,2900.03 key1.2 ; U2.7 3250.16,3510.16 3238.19,3498.19 3238.19,3293.97 3256.85,3275.32 3259.68,3275.32 3280,3255 R10.1 3294.37,3194.32 3313.5,3194.32 3322.82,3185 3331.01,3185 3340.32,3194.32 3360.63,3194.32 C9.2
  Bottom Layer w7.87: P3.9 2095,3895 2075,3875 2075,3015 2085,3005 v1(2100,3005) 2158.16,2946.84 3247.28,2946.84 3325,3024.56 v1(3325,3175)
OSC_IN: C13.1 U2.5 Y1.1 | length 387.2
  Top Layer w8: Y1.1 3208.55,3620 3218.55,3610 3218.55,3556.46 3225.43,3549.59 ; 3225.43,3549.53 3305.38,3549.53 3305.55,3549.7 U2.5
  Top Layer w19.68: C13.1 3094.68,3670.32 Y1.1
OSC_OUT: C14.1 U2.6 Y1.2 | length 420.5
  Top Layer w7.87: 3225.43,3529.84 U2.6
  Top Layer w8: Y1.2 3148,3425 3213.75,3425 3218.44,3429.69 3218.44,3522.73 3225.43,3529.72
  Top Layer w19.68: C14.1 3106.69,3389.68 Y1.2
PF: U3.7 U8.2 | length 2611.1
  Top Layer w11.81: U3.7 4305.38,4251.99 4371.99,4251.99 4380,4260 4380,4295 4395,4310 5010,4310 5025,4295 5025,3065 5010,3050 4950,3050 4940,3040 4940,2865 4930,2855 U8.2
PF_MCU: R35.2 U2.29 | length 975.9
  Top Layer w10: U2.29 3674.53,3490.47 3683.35,3481.65 3683.35,3355 3701.85,3336.49 3733.98,3336.49 3745.47,3325 3745.47,2884.53 3760,2870 v2(3825,2870) ; v2(3959.38,2869.38) 3960,2870 R35.2
  Bottom Layer w10: v2(3825,2870) 3825.62,2869.38 v2(3959.38,2869.38)
RX: R22.1 U3.8 U4.4 | length 2834.6
  Top Layer w11.81: U3.8 4302.87,4305.51 4353.08,4305.51 4360,4312.43 4360,4325 4369.21,4334.21 5035.79,4334.21 5050,4320 5050,3050 5025,3025 4975,3025 4965,3015 4965,2765 4895,2695 4755,2695 4740,2680 4740,2625.04 4739.96,2625 U4.4
SCL1: R7.2 U2.42 | length 1183.4
  Top Layer w7.87: R7.2 2860,2998.15 v5(2860,3000) ; U2.42 3474.84,3605.16 v1(3485,3595)
  Bottom Layer w7.87: v5(2860,3000) 3057.69,3197.69 3178.89,3197.69 3206.45,3225.25 3411.67,3225.25 3440,3253.58 3440,3510 3485,3555 v1(3485,3595)
SDA1: R8.2 U2.43 | length 1450.4
  Top Layer w7.87: R8.2 v5(2560,3000) ; v1(3440,3590) 3455,3605 3455,3679.29 U2.43
  Bottom Layer w7.87: v5(2560,3000) 2596.5,3036.5 2868.4,3036.5 3049.46,3217.56 3111.36,3217.56 3138.93,3245.13 3403.44,3245.13 3420,3261.69 3420,3535.39 3440,3555.39 v1(3440,3590)
SPK: R36.1 U2.28 | length 771.8
  Top Layer w7.87: R36.1 3165,3195 v1(3215,3195) ; v1(3550,3470.79) U2.28
  Bottom Layer w7.87: v1(3215,3195) 3306.2,3195 3313.64,3202.44 3429.08,3202.44 3448.64,3182.88 3471.36,3182.88 3487.44,3198.95 3487.44,3242.44 3464.41,3265.46 3464.41,3459.41 3475,3470 v1@3540,3470
SWCLK: P3.7 U2.37 | length 1696.4
  Top Layer w7.87: v4(3570.04,3835) 3572.67,3832.37 3572.67,3680.05 U2.37
  Bottom Layer w7.87: P3.7 3075,3695 3075,3800 3110,3835 v4(3570.04,3835)
SWDIO: P3.6 U2.34 | length 1986.9
  Top Layer w11.81: U2.34 3680.63,3588.9 3690,3598.27 3690,3629.84 3689.84,3630 3689.84,3780 3669.84,3800 v4(3624.45,3800)
  Bottom Layer w11.81: P3.6 2210,3595 2225.11,3610.11 2225,3610.22 2225,3670 3105,3670 3105,3785 3120,3800 v4(3624.45,3800)
TX: U3.6 U5.2 | length 2321.5
  Top Layer w11.81: U3.6 4395.04,4205 4405,4214.96 4405,4265 4420,4280 4985,4280 5000,4265 5000,3105 4975,3080 U5.2
USART1_RX: R29.2 U2.31 | length 811.1
  Top Layer w11: U2.31 3705.16,3529.84
  Top Layer w11.81: 3705.16,3529.84 3725,3510 3725,3399.68 3735,3389.68 3790.32,3389.68 3805,3375 3805,3085 3820,3070 R29.2
USART1_TX: R30.1 U2.30 | length 1331.9
  Top Layer w11: U2.30 3689.84,3510.16
  Top Layer w11.81: 3689.84,3510.16 3703.19,3496.81 3703.19,3376.81 3715,3365 3774.27,3365 3781.19,3358.08 3781.19,2928.81 3795,2915 3860,2915 3870,2905 3870,2540 3890,2520 R30.1
USART2_RX: P3.3 U2.13 | length 1234
  Top Layer w11.81: v2(3320,3335) 3320,3338.09 3342.47,3360.55 U2.13@3355,3360.55
  Bottom Layer w11.81: P3.3 2190,3335 v2(3320,3335)
USART2_TX: P3.4 U2.12 | length 1197.4
  Top Layer w11.81: v2(3290,3365) U2.12@3290,3410
  Bottom Layer w11.81: P3.4 2161.33,3395 2191.33,3365 v2(3290,3365)
USART3_RX: M2.8 P4.2 U2.22 | length 2292.4
  Top Layer w11: 3533.9,3310 U2.22
  Top Layer w11.81: 3534.03,3310 3534.22,3310 3550,3294.22 v1(3550,3265)
  Bottom Layer w11.81: P4.2 3090,2020 3075,2005 3075,1881.92 3068.08,1875 M2.8 2931.92,1875 2925,1881.92 2925,2245 2917.33,2252.67 2917.33,2871 2947.52,2901.19 3274.86,2901.19 3382.76,3009.09 3382.76,3017.76 3550,3185 v1(3550,3265)
USART3_TX: M2.1 P4.3 U2.21 | length 2159.7
  Top Layer w11: v1@3514.21,3280.79 U2.21
  Top Layer w11.81: M2.1 2875,2131.92 2881.92,2125 3030,2125 3050,2105 3050,1932.25 3062.25,1920 P4.3 ; v1@3514.21,3280.79 v1(3515,3280)
  Bottom Layer w11.81: M2.1 2875,2905 2895,2925 3256.33,2925 3515,3183.67 v1(3515,3280)
WIFI_EN: M2.7 R37.1 U2.25 | length 2134.9
  Top Layer w11.81: v1(2946.73,2380) R37.1 ; U2.25 3624.61,3411.73 3625,3411.34 v1(3625,3340)
  Bottom Layer w11.81: M2.7 3020,1975 3030,1985 3030,2283.08 3023.08,2290 2956.73,2290 2946.73,2300 v1(2946.73,2380) 2946.73,2866.73 2957.38,2877.38 3284.73,2877.38 3406.57,2999.22 3406.57,3003.16 3528.41,3125 3610,3125 3625,3140 v1(3625,3340)
pads on no net: M1.4 M2.2 M2.3 M2.6 U2.1 U2.2 U2.3 U2.4 U2.10 U2.14 U2.15 U2.16 U2.17 U2.19 U2.26 U2.27 U2.32 U2.33 U2.38 U2.39 U2.40 U2.45 U2.46 U7.0 U7.3 U7.4 USB1.0 USB1.2 USB1.3 USB1.6 USB1.7
copper on no net:
  other v1: 2335,3115

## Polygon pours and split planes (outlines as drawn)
DGND on Top Layer "Top Layer-DGND" (solid, pour order 70): 3820,4055 3840,4035 3840,3190 3845,3185 4330,3185 4330,1730 4032.32,1730 4032.32,2002.64 4029.96,2005 3204.21,2005 3204.21,1733.19 3207.36,1730.04 3207.32,1730 2045,1730 2042.5,1732.5 2050,1740 2050,4055
DGND on Top Layer "Top Layer-DGND 1" (solid, pour order 54): 1565,4070
DGND on Top Layer "Top Layer-No Net" (solid, shelved, pour order 40): 2015,4031.46 2025.07,4041.53 3906.07,4041.53 4405,3542.6 4380,3517.6 4380,1725 2050,1725 2035,1740
no net on Top Layer "NONET_L01_P010" (solid, remove dead copper, shelved, pour order 10): 2951.94,4014.29 3716.94,4014.29 3716.94,3169.29 2951.94,3169.29
no net on Top Layer "Keep-Out Layer-No Net" (solid, remove dead copper, shelved, pour order 14): 2935,4030 3715,4030 3715,3180 3710,3175 2935,3175
no net on Top Layer "Keep-Out Layer-No Net" (solid, remove dead copper, shelved, pour order 18): 2890,3980 3725,3980 3725,3095.08 2905.22,3095.08 2890.04,3080
no net on Top Layer "Keep-Out Layer-No Net" (solid, remove dead copper, shelved, pour order 22): 3690,3185 3690,3975 2945,3975 2945,3170
DGND on Bottom Layer "Bottom Layer-DGND" (solid, pour order 68): 2047.55,4055 3830,4055 3830,3190 4330,3190 4330,1730 4032.32,1730 4032.32,2000 4027.32,2005 3210,2005 3207.36,2007.64 3207.36,1730.04 2045.01,1730.04 2045,1730.05 2045,4052.45
DGND on Bottom Layer "Bottom Layer-DGND 2" (solid, pour order 62): 16040,3395
DGND on Bottom Layer "Bottom Layer-No Net" (solid, shelved, pour order 38): 2045.05,4035 2050.05,4040 3915,4040 4410,3545 4390,3525 4390,1730 2030,1730 2025,1725
DGND on Bottom Layer "Bottom Layer-No Net 1" (solid, shelved, pour order 36): 2045.05,4035 2050.05,4040 3910,4040 4400,3550 4400,1730 2035,1730 2030,1735
DGND on Bottom Layer "Bottom Layer-No Net 2" (hatched Horizontal grid 20 track 8, shelved, pour order 30): 45040,3775
DGND on Bottom Layer "Bottom Layer-DGND 1" (solid, shelved, pour order 26): 39250,4345
no net on Bottom Layer "Keep-Out Layer-No Net" (solid, remove dead copper, shelved, pour order 8): 2946.73,4015.65 3707.1,4015.65 3711.73,4010.65 3711.73,3170.65 2946.73,3170.65
no net on Bottom Layer "Keep-Out Layer-No Net" (solid, remove dead copper, shelved, pour order 12): 2935,4030 3715,4030 3715,3175 2935,3175
no net on Bottom Layer "Keep-Out Layer-No Net" (solid, remove dead copper, shelved, pour order 16): 2865,4015 3710,4015 3715,4010 3715,3115 2860,3115
no net on Bottom Layer "NONET_L02_P020" (solid, remove dead copper, shelved, pour order 20): 2945,3975 3690,3975 3690,3185 2945,3185

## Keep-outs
Keep-Out Layer:
  lines w7.5: 2045,1805 ccw(c2119.95,1805) 2119.95,1730.05 ; 2045.05,4744.46 cw(c2120,4744.46) 2120,4819.41 ; 5119.65,4819.41 cw(c5119.65,4744.46) 5194.61,4744.46 ; 5135,1730 ccw(c5135,1790) 5195,1790
  lines w7.87: 2045,1805 2045,4744.46 ; 2119.95,1730.05 2119.95,1730 3207.32,1730 ; 2120,4819.41 5119.65,4819.41 ; 3207.36,1730.04 3207.36,1925.71 ; 4032.32,1925.71 4032.32,1730 5135,1730 ; 4615,3190 3830,3190 3830,3950 4615,3950 ; 5194.61,1790 5194.61,4744.46
  lines w10: 3207.36,1926.42 cw(c3619.84,1926.42) 4032.32,1926.42 ; 4615,3190 4615,3660 4775,3660 4780,3665 4780,3950 4615,3950

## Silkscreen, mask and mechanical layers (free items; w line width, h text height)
Top Overlay:
  text "AC~IN" at 4790,4740 h39.37
  text "NRST" at 2230,3925 h25 r270
  text "3V3" at 2225,3815 h25 r270
  text "CLK" at 2225,3725 h25 r270
  text "DIO" at 2220,3628.27 h25 r270
  text "GND" at 2215,3525 h25 r270
  text "TX" at 2212.32,3420 h25 r270
  text "RX" at 2210,3315 h25 r270
  text "SDA" at 2212.32,3230 h25 r270
  text "SCL" at 2212.32,3125 h25 r270
  text "3V3" at 3075,2090 h31.5 r90
  text "RX" at 3080,2000 h31.5 r90
  text "TX" at 3080,1895 h31.5 r90
  text "AC~OUT" at 4950,1785 h39.37
  text "GND" at 3080,1770 h31.5 r90
Bottom Overlay:
  text "wang.david.wei@scu.iot.lab" at 3845,4685 h60
  text "powerblade plus v3.0 2019.04.12" at 4475,4540 h60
